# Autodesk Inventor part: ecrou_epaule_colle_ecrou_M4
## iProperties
Created: 2011-01
Part Number: ecrou_epaule_colle_ecrou_M4
Document SubType Name: Modeling
Designer: eric
Density: 1 g/cm^3
Mass: 0.070945 g
Surface Area: 1.50655 cm^2
Volume: 0.070945 cm^3
Author: eric
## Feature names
1. Base1
